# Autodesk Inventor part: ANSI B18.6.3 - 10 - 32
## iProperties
Comments: To add or edit properties for Autodesk Inventor files, use iProperties.
Created: 2005-01
Part Number: ANSI B18.6.3 - 10 - 32
Vendor: Autodesk Inc.
Document SubType Name: Modeling
Designer: John Blackburn
Material: Default
Description: Hex Machine Screw Nut UNF
Standard: ANSI B18.6.3
Size Designation: 10 - 32
Alert: To add or edit properties for Autodesk Inventor files, use iProperties.
Control State: 0
Master: False
Checked Out: False
Shininess: 64.0
Length Units: 11272
Angle Units: 11279
Time Units: 11290
Mass Units: 11286
Length Display Precision: 3
Angle Display Precision: 2
Compacted: True
EGR: 4
Classification: un/spsc 31161727
Density: 0.0
Volumn: 0.0
Area: 0.0
PropertySet Name: Model Information
Author: John Blackburn
Revision Number: 8
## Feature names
1. Body [Extrusion]
2. Chamfer1 [Revolution]
3. Thread [Hole]
4. Chamfer2
5. Chamfer3
